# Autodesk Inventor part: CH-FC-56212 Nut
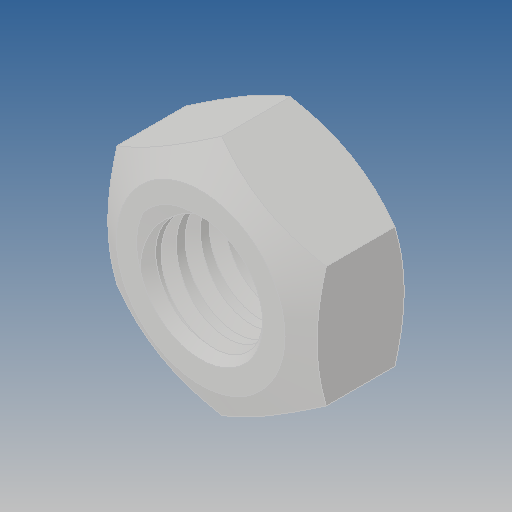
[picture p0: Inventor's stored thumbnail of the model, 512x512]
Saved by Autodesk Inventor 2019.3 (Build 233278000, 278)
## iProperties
Created: 2017-11
Part Number: CH-FC-56212 Nut
Material: Ogólny
Document SubType Name: Modeling
Designer: Admin
Density: 1 g/cm^3
Appearance: Domyślna
Author: Admin
Revision Number: ÈÎºÎ
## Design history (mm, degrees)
feature "¾µÏò1"
node "Bryła1"
